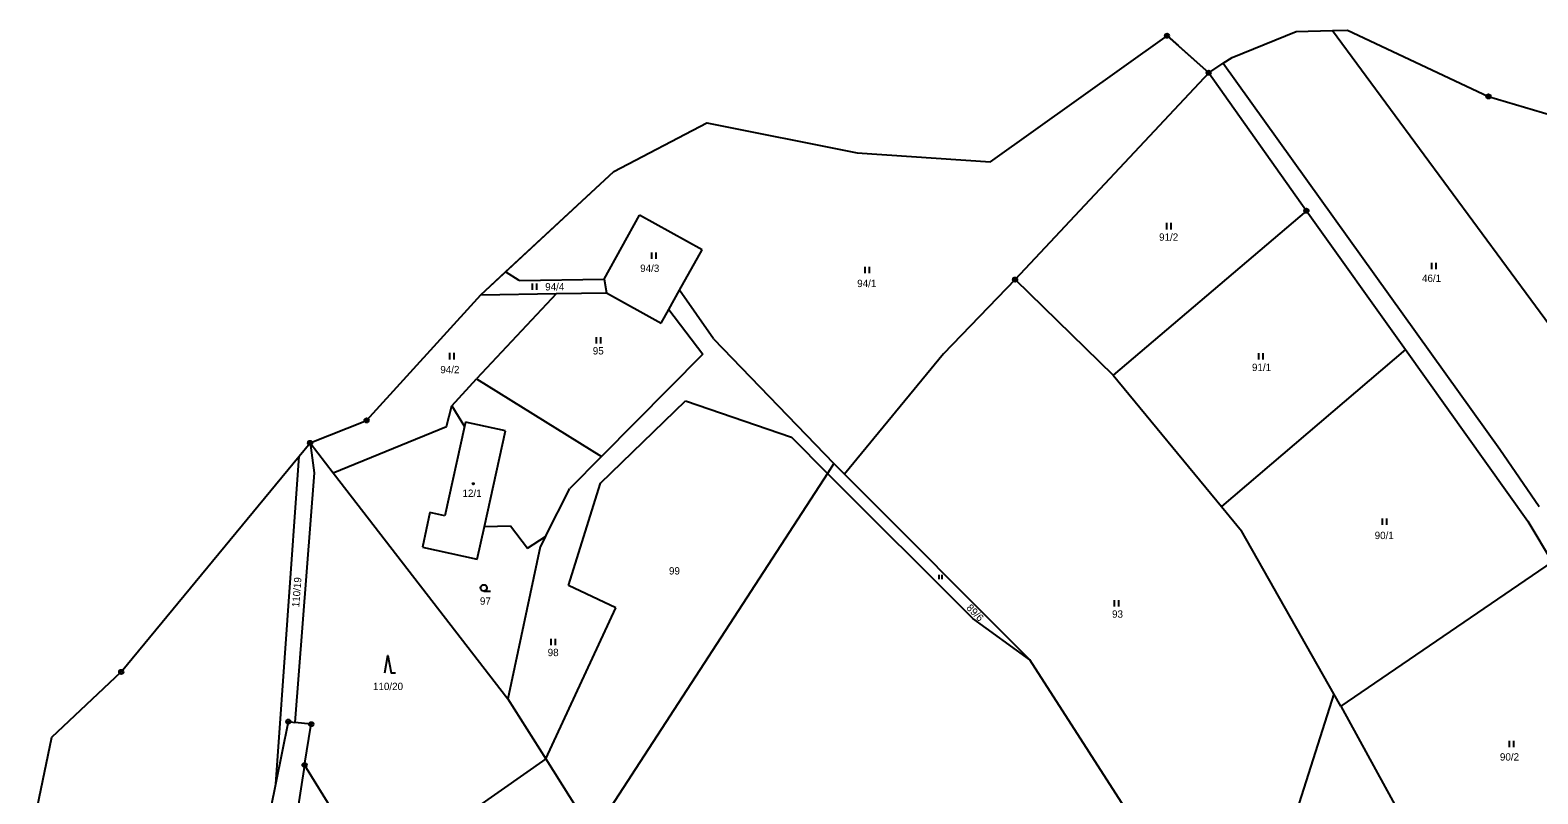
# Model space of a CAD drawing. Extents: x -445050 to -440454, y -1134563 to -1129741.
# Drawn here: x -441931.7 to -441582.9, y -1129917.7 to -1129741.1 of the extents above; entities that cross this region are included whole.
import ezdxf

# ---------------------------------------------------------------- set-up
doc = ezdxf.new("R2010")
doc.units = 0
for name, color, linetype in [('Vrstva 1', 7, 'Continuous'), ('Vrstva 13', 7, 'Continuous'), ('Vrstva 18', 7, 'Continuous'), ('Vrstva 19', 7, 'Continuous'), ('Vrstva 24', 7, 'Continuous'), ('Vrstva 25', 7, 'Continuous'), ('Vrstva 3', 7, 'Continuous'), ('Vrstva 37', 7, 'Continuous'), ('Vrstva 4', 7, 'Continuous'), ('Vrstva 52', 7, 'Continuous'), ('Vrstva 6', 7, 'Continuous')]:
    doc.layers.add(name, color=color, linetype=linetype)

msp = doc.modelspace()

# ---------------------------------------------------------------- linework, layer by layer
at = {"layer": 'Vrstva 1'}
for p, q in [((-441776.3, -1129791.9), (-441790.76, -1129783.9)), ((-441781.48, -1129801.21), (-441776.3, -1129791.9)), ((-441818.59, -1129798.98), (-441821.73, -1129796.96)), ((-441798.95, -1129798.67), (-441798.41, -1129801.83)), ((-441809.93, -1129802.02), (-441828.45, -1129821.75)), ((-441827.5, -1129802.31), (-441809.93, -1129802.02)), ((-441809.93, -1129802.02), (-441798.41, -1129801.83)), ((-441798.41, -1129801.83), (-441785.74, -1129808.87)), ((-441783.98, -1129805.7), (-441781.48, -1129801.21)), ((-441773.65, -1129812.47), (-441781.48, -1129801.21)), ((-441785.74, -1129808.87), (-441783.98, -1129805.7)), ((-441783.98, -1129805.7), (-441776.14, -1129815.99))]:
    msp.add_line(p, q, dxfattribs=at)
for points in [[(-441659.09, -1129750.95), (-441703.89, -1129798.76)], [(-441659.09, -1129750.95), (-441636.47, -1129782.87)], [(-441655.75, -1129748.76), (-441591.72, -1129837.97)], [(-441798.95, -1129798.67), (-441790.76, -1129783.9)], [(-441636.47, -1129782.87), (-441613.59, -1129814.92)], [(-441818.59, -1129798.98), (-441798.95, -1129798.67)], [(-441703.89, -1129798.76), (-441720.4, -1129815.92)], [(-441773.65, -1129812.47), (-441745.79, -1129841.34)], [(-441776.14, -1129815.99), (-441799.57, -1129839.69)], [(-441720.4, -1129815.92), (-441743.36, -1129843.79)], [(-441613.59, -1129814.92), (-441585.24, -1129854.64)], [(-441834.16, -1129827.94), (-441828.45, -1129821.75)], [(-441828.45, -1129821.75), (-441799.57, -1129839.69)], [(-441835.38, -1129832.77), (-441834.16, -1129827.94)], [(-441834.16, -1129827.94), (-441831.27, -1129832.72)], [(-441799.78, -1129845.87), (-441780.14, -1129826.83)], [(-441780.14, -1129826.83), (-441755.62, -1129835.19)], [(-441861.64, -1129843.44), (-441835.38, -1129832.77)], [(-441831.27, -1129832.72), (-441835.81, -1129853.4)], [(-441866.98, -1129836.53), (-441861.64, -1129843.44)], [(-441866.98, -1129836.53), (-441866.02, -1129843.44)], [(-441755.62, -1129835.19), (-441747.29, -1129843.65)], [(-441591.72, -1129837.97), (-441582.64, -1129851.25)], [(-441874.92, -1129915.47), (-441869.52, -1129839.61)], [(-441799.57, -1129839.69), (-441806.9, -1129847.12)], [(-441745.79, -1129841.34), (-441747.29, -1129843.65)], [(-441745.79, -1129841.34), (-441743.36, -1129843.79)], [(-441866.02, -1129843.44), (-441870.5, -1129901.16)], [(-441861.64, -1129843.44), (-441821.24, -1129895.7)], [(-441747.29, -1129843.65), (-441801.46, -1129927.04)], [(-441812.49, -1129858.19), (-441806.9, -1129847.12)], [(-441807.18, -1129869.52), (-441799.78, -1129845.87)], [(-441839.23, -1129852.65), (-441840.99, -1129860.66)], [(-441835.81, -1129853.4), (-441839.23, -1129852.65)], [(-441828.29, -1129863.45), (-441826.64, -1129855.91)], [(-441826.64, -1129855.91), (-441820.59, -1129855.71)], [(-441820.59, -1129855.71), (-441816.7, -1129860.86)], [(-441585.24, -1129854.64), (-441579.66, -1129864.06)], [(-441816.7, -1129860.86), (-441812.49, -1129858.19)], [(-441812.49, -1129858.19), (-441813.71, -1129860.6)], [(-441840.99, -1129860.66), (-441828.29, -1129863.45)], [(-441813.71, -1129860.6), (-441821.24, -1129895.7)], [(-441796.21, -1129874.68), (-441807.18, -1129869.52)], [(-441812.45, -1129909.61), (-441796.21, -1129874.68)], [(-441821.24, -1129895.7), (-441812.45, -1129909.61)], [(-441874.92, -1129915.47), (-441871.99, -1129901)], [(-441871.99, -1129901), (-441870.5, -1129901.16)], [(-441866.69, -1129901.58), (-441870.5, -1129901.16)], [(-441868.23, -1129911.04), (-441866.69, -1129901.58)], [(-441868.23, -1129911.04), (-441873.11, -1129942.42)], [(-441868.23, -1129911.04), (-441854.5, -1129933.25)], [(-441812.45, -1129909.61), (-441833.86, -1129924.66)], [(-441812.45, -1129909.61), (-441801.46, -1129927.04)], [(-441880.06, -1129940.9), (-441874.92, -1129915.47)]]:
    msp.add_lwpolyline(points, dxfattribs=at)
at = {"layer": 'Vrstva 13'}
for points in [[(-441709.58, -1129771.58), (-441668.73, -1129742.39)], [(-441668.73, -1129742.39), (-441659.09, -1129750.95)], [(-441653.67, -1129747.4), (-441638.81, -1129741.44)], [(-441638.81, -1129741.44), (-441630.48, -1129741.2)], [(-441630.48, -1129741.2), (-441627.01, -1129741.1)], [(-441627.01, -1129741.1), (-441594.36, -1129756.43)], [(-441655.75, -1129748.76), (-441653.67, -1129747.4)], [(-441659.09, -1129750.95), (-441655.75, -1129748.76)], [(-441594.36, -1129756.43), (-441548.54, -1129769.98)], [(-441796.73, -1129773.78), (-441775.18, -1129762.53)], [(-441775.18, -1129762.53), (-441740.41, -1129769.48)], [(-441740.41, -1129769.48), (-441709.58, -1129771.58)], [(-441821.73, -1129796.96), (-441796.73, -1129773.78)], [(-441827.5, -1129802.31), (-441821.73, -1129796.96)], [(-441853.91, -1129831.34), (-441827.5, -1129802.31)], [(-441866.98, -1129836.53), (-441853.91, -1129831.34)], [(-441869.52, -1129839.61), (-441866.98, -1129836.53)], [(-441910.67, -1129889.51), (-441869.52, -1129839.61)], [(-441926.71, -1129904.58), (-441910.67, -1129889.51)], [(-441931.73, -1129928.7), (-441926.71, -1129904.58)]]:
    msp.add_lwpolyline(points, dxfattribs=at)
at = {"layer": 'Vrstva 24'}
for centre, radius in [((-441668.73, -1129742.39), 0.5), ((-441668.73, -1129742.39), 0.1), ((-441659.09, -1129750.95), 0.5), ((-441659.09, -1129750.95), 0.1), ((-441594.36, -1129756.43), 0.5), ((-441594.36, -1129756.43), 0.1), ((-441636.47, -1129782.87), 0.5), ((-441636.47, -1129782.87), 0.1), ((-441703.89, -1129798.76), 0.5), ((-441703.89, -1129798.76), 0.1), ((-441853.91, -1129831.34), 0.5), ((-441853.91, -1129831.34), 0.1), ((-441866.98, -1129836.53), 0.5), ((-441866.98, -1129836.53), 0.1), ((-441910.67, -1129889.51), 0.5), ((-441910.67, -1129889.51), 0.1), ((-441871.99, -1129901), 0.5), ((-441871.99, -1129901), 0.1), ((-441866.69, -1129901.58), 0.5), ((-441866.69, -1129901.58), 0.1), ((-441868.23, -1129911.04), 0.5), ((-441868.23, -1129911.04), 0.1)]:
    msp.add_circle(centre, radius, dxfattribs=at)
at = {"layer": 'Vrstva 25'}
for p, q in [((-441668.78, -1129787.19), (-441668.78, -1129785.69)), ((-441667.78, -1129787.19), (-441667.78, -1129785.69)), ((-441787.94, -1129794.01), (-441787.94, -1129792.51)), ((-441786.94, -1129794.01), (-441786.94, -1129792.51)), ((-441738.56, -1129797.32), (-441738.56, -1129795.82)), ((-441737.56, -1129797.32), (-441737.56, -1129795.82)), ((-441607.48, -1129796.38), (-441607.48, -1129794.88)), ((-441606.48, -1129796.38), (-441606.48, -1129794.88)), ((-441815.48, -1129801.15), (-441815.48, -1129799.65)), ((-441814.48, -1129801.15), (-441814.48, -1129799.65)), ((-441800.72, -1129813.59), (-441800.72, -1129812.09)), ((-441799.72, -1129813.59), (-441799.72, -1129812.09)), ((-441834.62, -1129817.25), (-441834.62, -1129815.75)), ((-441833.62, -1129817.25), (-441833.62, -1129815.75)), ((-441647.5, -1129817.29), (-441647.5, -1129815.79)), ((-441646.5, -1129817.29), (-441646.5, -1129815.79)), ((-441618.91, -1129855.49), (-441618.91, -1129853.99)), ((-441617.91, -1129855.49), (-441617.91, -1129853.99)), ((-441721.45, -1129868.06), (-441721.45, -1129867.05)), ((-441720.78, -1129868.06), (-441720.78, -1129867.05)), ((-441826.8, -1129870.84), (-441825.2, -1129870.84)), ((-441680.84, -1129874.37), (-441680.84, -1129872.87)), ((-441679.84, -1129874.37), (-441679.84, -1129872.87)), ((-441811.21, -1129883.32), (-441811.21, -1129881.82)), ((-441810.21, -1129883.32), (-441810.21, -1129881.82)), ((-441589.53, -1129906.92), (-441589.53, -1129905.42)), ((-441588.53, -1129906.92), (-441588.53, -1129905.42))]:
    msp.add_line(p, q, dxfattribs=at)
msp.add_lwpolyline([(-441849.68, -1129889.7), (-441848.98, -1129885.7), (-441848.18, -1129889.7), (-441847.18, -1129889.7)], dxfattribs=at)
for centre, radius in [((-441829.23, -1129845.99), 0.175), ((-441826.8, -1129870.09), 0.75)]:
    msp.add_circle(centre, radius, dxfattribs=at)
at = {"layer": 'Vrstva 3'}
for points in [[(-441831.27, -1129832.72), (-441835.81, -1129853.4)], [(-441831.05, -1129831.72), (-441831.27, -1129832.72)], [(-441821.77, -1129833.76), (-441831.05, -1129831.72)], [(-441826.64, -1129855.91), (-441821.77, -1129833.76)], [(-441839.23, -1129852.65), (-441840.99, -1129860.66)], [(-441835.81, -1129853.4), (-441839.23, -1129852.65)], [(-441828.29, -1129863.45), (-441826.64, -1129855.91)], [(-441840.99, -1129860.66), (-441828.29, -1129863.45)]]:
    msp.add_lwpolyline(points, dxfattribs=at)
at = {"layer": 'Vrstva 37'}
msp.add_circle((-441829.23, -1129845.99), 0.175, dxfattribs=at)
at = {"layer": 'Vrstva 4'}
for points in [[(-441831.05, -1129831.72), (-441831.27, -1129832.72)], [(-441821.77, -1129833.76), (-441831.05, -1129831.72)], [(-441826.64, -1129855.91), (-441821.77, -1129833.76)]]:
    msp.add_lwpolyline(points, dxfattribs=at)
at = {"layer": 'Vrstva 52'}
for points in [[(-441931.73, -1129928.7), (-441926.71, -1129904.58), (-441910.67, -1129889.51), (-441869.52, -1129839.61), (-441866.98, -1129836.53), (-441853.91, -1129831.34), (-441827.5, -1129802.31), (-441796.73, -1129773.78), (-441775.18, -1129762.53), (-441740.41, -1129769.48), (-441709.58, -1129771.58), (-441668.73, -1129742.39), (-441666.17, -1129744.67), (-441659.09, -1129750.95), (-441655.75, -1129748.76), (-441653.67, -1129747.4), (-441638.81, -1129741.44), (-441630.48, -1129741.2), (-441627.01, -1129741.1)], [(-441627.01, -1129741.1), (-441594.36, -1129756.43), (-441548.54, -1129769.98)]]:
    msp.add_lwpolyline(points, dxfattribs=at)
at = {"layer": 'Vrstva 6'}
for points in [[(-441630.48, -1129741.2), (-441563.33, -1129832.15)], [(-441636.47, -1129782.87), (-441681.22, -1129820.9)], [(-441703.89, -1129798.76), (-441681.22, -1129820.9)], [(-441613.59, -1129814.92), (-441656.09, -1129851.25)], [(-441681.22, -1129820.9), (-441656.09, -1129851.25)], [(-441713.64, -1129877.15), (-441747.29, -1129843.65)], [(-441743.36, -1129843.79), (-441700.5, -1129886.72)], [(-441656.09, -1129851.25), (-441651.46, -1129856.85)], [(-441630.11, -1129894.56), (-441651.46, -1129856.85)], [(-441579.66, -1129864.06), (-441628.48, -1129897.43)], [(-441700.5, -1129886.72), (-441713.64, -1129877.15)], [(-441673.03, -1129929.43), (-441700.5, -1129886.72)], [(-441630.11, -1129894.56), (-441640.87, -1129928.28)], [(-441628.48, -1129897.43), (-441630.11, -1129894.56)], [(-441628.48, -1129897.43), (-441606.73, -1129937.28)]]:
    msp.add_lwpolyline(points, dxfattribs=at)

# ---------------------------------------------------------------- texts
at = {"layer": 'Vrstva 18'}
for s, p in [('91/2', (-441670.56, -1129789.8)), ('94/3', (-441790.61, -1129797.01)), ('94/4', (-441812.58, -1129801.29)), ('94/1', (-441740.4, -1129800.51)), ('46/1', (-441609.74, -1129799.32)), ('95', (-441801.57, -1129816.09)), ('94/2', (-441836.84, -1129820.44)), ('91/1', (-441649.07, -1129819.92)), ('90/1', (-441620.69, -1129858.78)), ('99', (-441783.94, -1129866.98)), ('97', (-441827.68, -1129873.96)), ('93', (-441681.44, -1129876.97)), ('98', (-441812, -1129885.85)), ('110/20', (-441852.42, -1129893.7)), ('90/2', (-441591.71, -1129910))]:
    msp.add_text(s, height=1.7, dxfattribs=at).set_placement(p)
for s, rotation, p in [('110/19', 85.5054, (-441869.49, -1129874.6)), ('89/6', 314.3736, (-441715.27, -1129874.82))]:
    msp.add_text(s, height=1.7, rotation=rotation, dxfattribs=at).set_placement(p)
at = {"layer": 'Vrstva 19'}
msp.add_text('12/1', height=1.7, dxfattribs=at).set_placement((-441831.71, -1129849.03))

doc.saveas('drawing.dxf')
